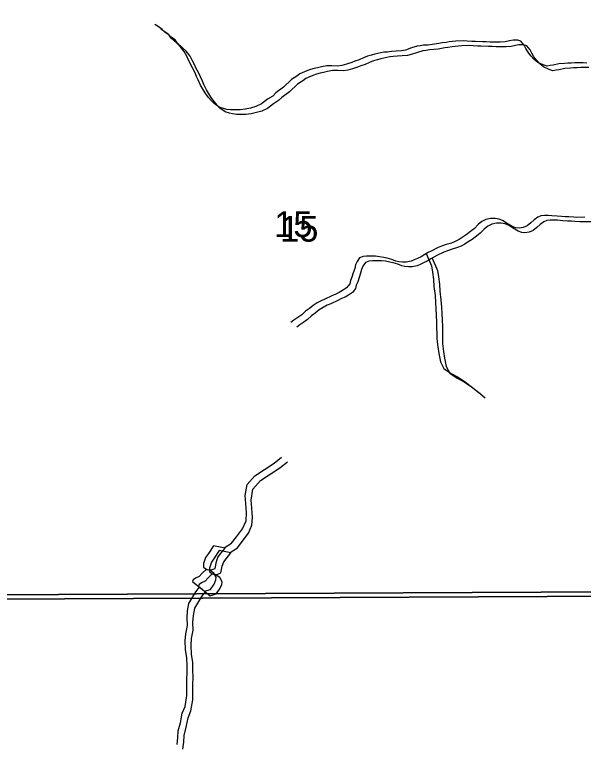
# Model space of a CAD drawing. Extents: x -21.1 to 50.3, y 0 to 22.1.
# Drawn here: x 47.215 to 48.142, y 16.437 to 17.623 of the extents above; entities that cross this region are included whole.
import ezdxf

# ---------------------------------------------------------------- set-up
doc = ezdxf.new("R2010")
doc.units = 0
for name, color, linetype in [('GM_X_Minor_Lake', 7, 'Continuous'), ('GM_X_Minor_River', 7, 'Continuous'), ('GM_X_Section', 7, 'Continuous'), ('GM_X_Section_Text', 7, 'Continuous')]:
    doc.layers.add(name, color=color, linetype=linetype)

msp = doc.modelspace()

# ---------------------------------------------------------------- linework, layer by layer
at = {"layer": 'GM_X_Minor_Lake'}
for points in [[(47.5394, 16.7587), (47.5312, 16.7461), (47.5267, 16.7396), (47.5234, 16.7297), (47.5234, 16.724), (47.5284, 16.7203), (47.5356, 16.7196), (47.5421, 16.7219), (47.5442, 16.733), (47.5468, 16.7398), (47.5505, 16.7448), (47.5584, 16.7547)], [(47.5584, 16.7547), (47.5394, 16.7587)], [(47.549, 16.7512), (47.5408, 16.7386), (47.5363, 16.7321), (47.533, 16.7222), (47.5331, 16.7165), (47.5381, 16.7128), (47.5453, 16.7121), (47.5517, 16.7144), (47.5538, 16.7255), (47.5564, 16.7323), (47.5602, 16.7373), (47.568, 16.7472)], [(47.568, 16.7472), (47.549, 16.7512)], [(47.5246, 16.6849), (47.5345, 16.6877), (47.5404, 16.6961), (47.5434, 16.703), (47.5437, 16.7075), (47.5402, 16.7143), (47.5341, 16.7184), (47.5273, 16.7199), (47.5213, 16.7141), (47.5164, 16.7088), (47.5104, 16.7057), (47.5062, 16.7033), (47.5055, 16.7003)], [(47.5343, 16.6774), (47.5441, 16.6802), (47.5501, 16.6886), (47.553, 16.6955), (47.5534, 16.7), (47.5499, 16.7068), (47.5438, 16.7109), (47.5369, 16.7124), (47.5309, 16.7066), (47.5261, 16.7013), (47.52, 16.6982), (47.5159, 16.6958), (47.5151, 16.6928)], [(47.5055, 16.7003), (47.5246, 16.6849)], [(47.5151, 16.6928), (47.5343, 16.6774)]]:
    msp.add_lwpolyline(points, dxfattribs=at)
at = {"layer": 'GM_X_Minor_River'}
for points in [[(47.5611, 17.469), (47.5557, 17.4702), (47.5489, 17.4724), (47.5405, 17.4784), (47.5359, 17.4833), (47.5313, 17.4886), (47.527, 17.4943), (47.5232, 17.5004), (47.5186, 17.5083), (47.5144, 17.517), (47.512, 17.5227), (47.509, 17.5295), (47.5055, 17.5364), (47.5013, 17.5439), (47.4982, 17.5508), (47.4959, 17.5557), (47.4916, 17.5633), (47.4851, 17.5712), (47.479, 17.5772), (47.4706, 17.5848), (47.4671, 17.5897), (47.461, 17.5939), (47.456, 17.5988), (47.4492, 17.604), (47.4438, 17.6071)], [(47.5707, 17.4615), (47.5654, 17.4627), (47.5585, 17.4649), (47.5501, 17.4709), (47.5455, 17.4758), (47.5409, 17.4811), (47.5367, 17.4868), (47.5328, 17.4929), (47.5282, 17.5008), (47.524, 17.5095), (47.5217, 17.5152), (47.5186, 17.522), (47.5151, 17.5289), (47.5109, 17.5364), (47.5078, 17.5433), (47.5055, 17.5482), (47.5013, 17.5558), (47.4948, 17.5637), (47.4886, 17.5697), (47.4802, 17.5773), (47.4768, 17.5822), (47.4707, 17.5864), (47.4657, 17.5913), (47.4588, 17.5965), (47.4535, 17.5996)], [(48.1476, 17.5444), (48.1415, 17.5448), (48.1282, 17.5447), (48.1221, 17.5443), (48.1168, 17.5442), (48.1114, 17.5438), (48.1023, 17.543), (48.0928, 17.5411), (48.0878, 17.5403), (48.0829, 17.5395), (48.0764, 17.5414), (48.0676, 17.5455), (48.0619, 17.55), (48.0565, 17.5561), (48.0519, 17.5621), (48.0485, 17.5682), (48.0454, 17.5735), (48.0404, 17.5799), (48.0351, 17.5818), (48.0275, 17.5818), (48.0218, 17.5806), (48.0145, 17.579), (48.0066, 17.5782), (47.9978, 17.5782), (47.9902, 17.5785), (47.9837, 17.5789), (47.9776, 17.5788), (47.9662, 17.5795), (47.9605, 17.5795), (47.9529, 17.5802), (47.9472, 17.5806), (47.9342, 17.5801), (47.9236, 17.5789), (47.9186, 17.5781), (47.9118, 17.5773), (47.9065, 17.5765), (47.8958, 17.5746), (47.889, 17.5738), (47.8817, 17.5734), (47.876, 17.5726), (47.8711, 17.5718), (47.862, 17.5691), (47.8521, 17.5656), (47.8456, 17.5644), (47.8373, 17.5636), (47.8297, 17.5632), (47.8228, 17.5624), (47.8171, 17.562), (47.8122, 17.5612), (47.8026, 17.5589), (47.7969, 17.5573), (47.7905, 17.5554), (47.784, 17.5527), (47.7768, 17.5496), (47.77, 17.5473), (47.7647, 17.5454), (47.7563, 17.5427), (47.7487, 17.5403), (47.7415, 17.5395), (47.7323, 17.5399), (47.724, 17.5398), (47.7156, 17.5383), (47.7091, 17.5367), (47.7034, 17.5355), (47.6977, 17.534), (47.6917, 17.5317), (47.6803, 17.5267), (47.6753, 17.5229), (47.6666, 17.5175), (47.6537, 17.5053), (47.6412, 17.4961), (47.6359, 17.4907), (47.6276, 17.4854), (47.6177, 17.4781), (47.6086, 17.4735), (47.5999, 17.4712), (47.5911, 17.4692), (47.5828, 17.468), (47.5725, 17.468), (47.5675, 17.4683), (47.5611, 17.469)], [(48.1511, 17.5373), (48.1378, 17.5372), (48.1317, 17.5368), (48.1264, 17.5367), (48.1211, 17.5363), (48.1119, 17.5355), (48.1024, 17.5336), (48.0975, 17.5328), (48.0925, 17.532), (48.0861, 17.5339), (48.0773, 17.538), (48.0715, 17.5425), (48.0662, 17.5486), (48.0616, 17.5546), (48.0581, 17.5607), (48.0551, 17.566), (48.0501, 17.5724), (48.0447, 17.5743), (48.0371, 17.5743), (48.0314, 17.5731), (48.0242, 17.5715), (48.0162, 17.5707), (48.0074, 17.5707), (47.9998, 17.571), (47.9934, 17.5714), (47.9873, 17.5713), (47.9758, 17.572), (47.9701, 17.572), (47.9625, 17.5727), (47.9568, 17.5731), (47.9439, 17.5726), (47.9332, 17.5714), (47.9283, 17.5706), (47.9214, 17.5698), (47.9161, 17.569), (47.9055, 17.5671), (47.8986, 17.5663), (47.8914, 17.5659), (47.8857, 17.5651), (47.8807, 17.5643), (47.8716, 17.5616), (47.8617, 17.5581), (47.8553, 17.5569), (47.8469, 17.5561), (47.8393, 17.5557), (47.8324, 17.5549), (47.8267, 17.5545), (47.8218, 17.5537), (47.8123, 17.5514), (47.8066, 17.5498), (47.8001, 17.5479), (47.7937, 17.5452), (47.7865, 17.5421), (47.7796, 17.5398), (47.7743, 17.5379), (47.7659, 17.5352), (47.7583, 17.5328), (47.7511, 17.532), (47.742, 17.5324), (47.7336, 17.5323), (47.7252, 17.5308), (47.7188, 17.5292), (47.7131, 17.528), (47.7074, 17.5265), (47.7013, 17.5242), (47.6899, 17.5192), (47.685, 17.5153), (47.6762, 17.51), (47.6634, 17.4978), (47.6509, 17.4886), (47.6456, 17.4832), (47.6372, 17.4779), (47.6274, 17.4706), (47.6183, 17.466), (47.6095, 17.4637), (47.6008, 17.4617), (47.5924, 17.4605), (47.5821, 17.4605), (47.5772, 17.4608), (47.5707, 17.4615)], [(48.1444, 17.2933), (48.1315, 17.2932), (48.1265, 17.2936), (48.1185, 17.2939), (48.1128, 17.2943), (48.1064, 17.2946), (48.0991, 17.2953), (48.0904, 17.296), (48.0846, 17.2964), (48.0786, 17.2964), (48.0729, 17.2956), (48.0679, 17.2936), (48.0618, 17.2891), (48.0565, 17.2841), (48.0505, 17.2795), (48.044, 17.2768), (48.0372, 17.2756), (48.0322, 17.276), (48.0261, 17.2782), (48.017, 17.2839), (48.0112, 17.2876), (48.0047, 17.2903), (47.9983, 17.2914), (47.9907, 17.2913), (47.9834, 17.2898), (47.9766, 17.2863), (47.9709, 17.2817), (47.9645, 17.2752), (47.9584, 17.2703), (47.9512, 17.2649), (47.9448, 17.2607), (47.9395, 17.2572), (47.9334, 17.2538), (47.9273, 17.2515), (47.9186, 17.2488), (47.911, 17.2461), (47.9053, 17.2441), (47.8939, 17.2384), (47.889, 17.2361), (47.884, 17.233), (47.878, 17.2292), (47.8719, 17.2265), (47.8666, 17.2242), (47.8616, 17.2219), (47.8533, 17.2203), (47.8476, 17.2203), (47.8415, 17.221), (47.8365, 17.2221), (47.83, 17.2244), (47.8224, 17.2266), (47.8171, 17.2277), (47.8098, 17.2292), (47.8033, 17.2299), (47.7946, 17.2302), (47.7889, 17.2302), (47.7832, 17.2294), (47.7775, 17.2271), (47.7733, 17.2214), (47.7711, 17.2157), (47.7696, 17.21), (47.7673, 17.2031), (47.7647, 17.1959), (47.7625, 17.1902), (47.7614, 17.1849), (47.7564, 17.1784), (47.7496, 17.1742), (47.7443, 17.1711), (47.7386, 17.1684), (47.7322, 17.1653), (47.7208, 17.1599), (47.7151, 17.1576)], [(48.1541, 17.2858), (48.1411, 17.2857), (48.1362, 17.2861), (48.1282, 17.2864), (48.1225, 17.2868), (48.116, 17.2871), (48.1088, 17.2878), (48.1, 17.2885), (48.0943, 17.2889), (48.0882, 17.2889), (48.0825, 17.2881), (48.0776, 17.2861), (48.0715, 17.2816), (48.0662, 17.2766), (48.0601, 17.272), (48.0537, 17.2693), (48.0468, 17.2681), (48.0419, 17.2685), (48.0358, 17.2707), (48.0266, 17.2764), (48.0209, 17.2801), (48.0144, 17.2828), (48.0079, 17.2839), (48.0003, 17.2838), (47.9931, 17.2823), (47.9862, 17.2788), (47.9806, 17.2742), (47.9741, 17.2677), (47.9681, 17.2628), (47.9609, 17.2574), (47.9544, 17.2532), (47.9491, 17.2497), (47.943, 17.2463), (47.937, 17.244), (47.9282, 17.2413), (47.9206, 17.2386), (47.9149, 17.2366), (47.9035, 17.2309), (47.8986, 17.2286), (47.8937, 17.2255), (47.8876, 17.2217), (47.8815, 17.219), (47.8762, 17.2167), (47.8713, 17.2144), (47.8629, 17.2128), (47.8572, 17.2128), (47.8511, 17.2135), (47.8461, 17.2146), (47.8397, 17.2169), (47.832, 17.2191), (47.8267, 17.2202), (47.8195, 17.2217), (47.813, 17.2224), (47.8042, 17.2227), (47.7985, 17.2227), (47.7928, 17.2219), (47.7871, 17.2196), (47.783, 17.2139), (47.7807, 17.2082), (47.7792, 17.2025), (47.777, 17.1956), (47.7744, 17.1884), (47.7721, 17.1827), (47.771, 17.1773), (47.7661, 17.1709), (47.7592, 17.1667), (47.7539, 17.1636), (47.7482, 17.1609), (47.7418, 17.1578), (47.7304, 17.1524), (47.7247, 17.1501)], [(47.8862, 17.2344), (47.8949, 17.2144), (47.8965, 17.2042), (47.8978, 17.192), (47.8987, 17.1807), (47.9004, 17.1663), (47.9013, 17.1545), (47.9018, 17.1439), (47.9023, 17.1344), (47.9028, 17.1223), (47.9031, 17.0953), (47.9047, 17.0825), (47.9064, 17.0715), (47.9092, 17.0582), (47.915, 17.0473), (47.9268, 17.0391), (47.9383, 17.0331), (47.9501, 17.0249), (47.9616, 17.0163), (47.9727, 17.0069)], [(47.8958, 17.2269), (47.9045, 17.2069), (47.9062, 17.1967), (47.9075, 17.1845), (47.9083, 17.1732), (47.91, 17.1588), (47.9109, 17.147), (47.9114, 17.1364), (47.9119, 17.1269), (47.9124, 17.1148), (47.9127, 17.0878), (47.9144, 17.075), (47.916, 17.064), (47.9188, 17.0507), (47.9246, 17.0398), (47.9365, 17.0316), (47.9479, 17.0256), (47.9598, 17.0174), (47.9712, 17.0088), (47.9823, 16.9994)], [(47.7151, 17.1576), (47.7082, 17.1542), (47.7018, 17.15), (47.6957, 17.145), (47.6893, 17.1404), (47.6832, 17.1347), (47.6768, 17.1301), (47.6703, 17.1259), (47.6654, 17.122)], [(47.7247, 17.1501), (47.7179, 17.1467), (47.7114, 17.1425), (47.7054, 17.1375), (47.6989, 17.1329), (47.6929, 17.1272), (47.6864, 17.1226), (47.68, 17.1184), (47.675, 17.1145)], [(47.5568, 16.7551), (47.5688, 16.7629), (47.5768, 16.7732), (47.587, 16.7865), (47.5926, 16.7995), (47.5933, 16.8124), (47.5924, 16.8276), (47.5912, 16.8405), (47.5942, 16.8584), (47.6067, 16.8725), (47.6381, 16.8932), (47.6503, 16.9028)], [(47.5664, 16.7476), (47.5785, 16.7554), (47.5864, 16.7657), (47.5966, 16.779), (47.6022, 16.792), (47.6029, 16.8049), (47.6021, 16.8201), (47.6009, 16.833), (47.6038, 16.8509), (47.6163, 16.865), (47.6478, 16.8857), (47.6599, 16.8953)], [(47.5336, 16.7185), (47.5344, 16.7197)], [(47.5433, 16.711), (47.5441, 16.7122)], [(47.4801, 16.435), (47.4815, 16.4464), (47.4822, 16.4574), (47.4856, 16.4707), (47.4885, 16.4863), (47.4931, 16.4973), (47.496, 16.5152), (47.4963, 16.5293), (47.4962, 16.5403), (47.4966, 16.5524), (47.4965, 16.5634), (47.496, 16.576), (47.4941, 16.5896), (47.4936, 16.6041), (47.4943, 16.6155), (47.4969, 16.6288), (47.4964, 16.6413), (47.4971, 16.6527), (47.4993, 16.6645), (47.5107, 16.6836), (47.5167, 16.6913)], [(47.4897, 16.4275), (47.4912, 16.4389), (47.4919, 16.4499), (47.4952, 16.4632), (47.4982, 16.4788), (47.5027, 16.4898), (47.5056, 16.5077), (47.5059, 16.5218), (47.5059, 16.5328), (47.5062, 16.5449), (47.5061, 16.5559), (47.5057, 16.5685), (47.5037, 16.5821), (47.5032, 16.5966), (47.5039, 16.608), (47.5065, 16.6213), (47.5061, 16.6338), (47.5068, 16.6452), (47.509, 16.657), (47.5203, 16.6761), (47.5263, 16.6838)]]:
    msp.add_lwpolyline(points, dxfattribs=at)
at = {"layer": 'GM_X_Section'}
for points in [[(47.1584, 17.6908), (48.171, 17.7091), (48.1855, 16.6839), (47.1739, 16.679)], [(47.168, 17.6833), (48.1806, 17.7016), (48.1952, 16.6764), (47.1836, 16.6715)], [(47.1739, 16.679), (48.1855, 16.6839), (48.1977, 15.669), (47.1998, 15.6592), (47.1908, 16.2808)], [(47.1836, 16.6715), (48.1952, 16.6764), (48.2073, 15.6615), (47.2094, 15.6517), (47.2004, 16.2733)]]:
    msp.add_lwpolyline(points, close=True, dxfattribs=at)

# ---------------------------------------------------------------- texts
at = {"layer": 'GM_X_Section_Text'}
for p in [(47.6384, 17.2612), (47.6481, 17.2537)]:
    msp.add_text('15', height=0.04186, rotation=0, dxfattribs=at).set_placement(p)

doc.saveas('drawing.dxf')
